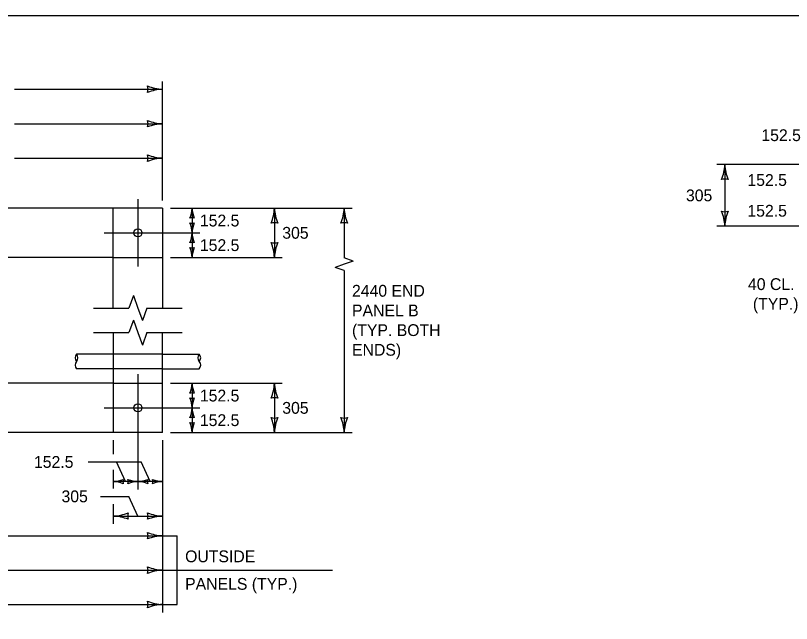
# Model space of a CAD drawing. Extents: x 49991.4 to 50021, y 49987.6 to 50011.4.
# Drawn here: x 50005.475 to 50009.419, y 49995.908 to 49998.999 of the extents above; entities that cross this region are included whole.
import ezdxf

# ---------------------------------------------------------------- set-up
doc = ezdxf.new("R2010")
doc.units = 0
for name, color, linetype in [('Level 1', 7, 'Continuous'), ('Level 2', 7, 'Continuous'), ('Level 3', 7, 'Continuous'), ('Level 4', 7, 'Continuous'), ('Level 5', 7, 'Continuous'), ('Level 6', 7, 'Continuous')]:
    doc.layers.add(name, color=color, linetype=linetype)

msp = doc.modelspace()

# ---------------------------------------------------------------- linework, layer by layer
at = {"layer": 'Level 1'}
for p, q in [((50006.2218, 49998.0191), (50005.1236, 49998.0191)), ((50005.9718, 49997.5116), (50005.9718, 49998.0191)), ((50006.2218, 49998.0191), (50006.2218, 49997.5116)), ((50005.9718, 49997.7691), (50005.1236, 49997.7691)), ((50005.9718, 49997.3866), (50005.9718, 49996.8791)), ((50006.2218, 49996.8791), (50006.2218, 49997.3866)), ((50005.9718, 49997.2773), (50005.7843, 49997.2773)), ((50006.2218, 49997.2773), (50006.4086, 49997.2773)), ((50005.9718, 49997.2023), (50005.7845, 49997.2023)), ((50006.2218, 49997.2023), (50006.4084, 49997.2023)), ((50005.9718, 49997.1291), (50005.1236, 49997.1291)), ((50006.2218, 49996.8791), (50005.1236, 49996.8791))]:
    msp.add_line(p, q, dxfattribs=at)
msp.add_lwpolyline([(49999.3835, 49998.9992), (50016.7501, 49998.9992), (50016.7501, 49987.7988), (49999.3835, 49987.7988)], close=True, dxfattribs=at)
for centre in [(50006.0967, 49997.8941), (50006.0967, 49997.0041)]:
    msp.add_circle(centre, 0.0208, dxfattribs=at)
for centre, radius, start, end in [((50005.8052, 49997.2585), 0.0281, 138.1897, 221.8103), ((50005.7633, 49997.2585), 0.0281, 318.1897, 41.8103), ((50006.4296, 49997.2585), 0.0281, 138.1897, 221.8103), ((50006.3877, 49997.2585), 0.0281, 318.1897, 41.8103), ((50005.8046, 49997.2212), 0.0276, 137.5252, 223.2656), ((50006.3885, 49997.2212), 0.0275, 316.52, 42.6892)]:
    msp.add_arc(centre, radius, start, end, dxfattribs=at)
at = {"layer": 'Level 3'}
for p, q in [((50006.2218, 49998.0591), (50006.2218, 49998.6641)), ((50005.469, 49998.6241), (50006.2218, 49998.6241)), ((50005.469, 49998.4491), (50006.2218, 49998.4491)), ((50005.4689, 49998.2741), (50006.2218, 49998.2741)), ((50009.5801, 49998.2408), (50009.0402, 49998.2408)), ((50009.0802, 49998.2408), (50009.0802, 49997.9282)), ((50006.2618, 49998.0191), (50007.1851, 49998.0191)), ((50006.3718, 49998.0191), (50006.3718, 49997.8941)), ((50006.7906, 49998.0191), (50006.7906, 49997.7691)), ((50007.1451, 49998.0191), (50007.1451, 49997.7668)), ((50009.8825, 49997.9282), (50009.0402, 49997.9282)), ((50006.3718, 49997.8941), (50006.3718, 49997.7691)), ((50006.2618, 49997.7691), (50006.8306, 49997.7691)), ((50007.1908, 49997.7506), (50007.1451, 49997.7668)), ((50007.1451, 49997.7344), (50007.0994, 49997.7182)), ((50007.1908, 49997.7506), (50007.1451, 49997.7344)), ((50007.1451, 49997.702), (50007.0994, 49997.7182)), ((50007.1451, 49997.702), (50007.1451, 49996.8791)), ((50006.2618, 49997.1291), (50006.8306, 49997.1291)), ((50006.3718, 49997.1291), (50006.3718, 49997.0041)), ((50006.7906, 49997.1291), (50006.7906, 49996.8791)), ((50006.3718, 49997.0041), (50006.3718, 49996.8791)), ((50006.2618, 49996.8791), (50007.1851, 49996.8791)), ((50005.9718, 49996.8391), (50005.9718, 49996.7691)), ((50006.2218, 49996.8391), (50006.2218, 49995.9641)), ((50005.8435, 49996.7291), (50006.1125, 49996.7291)), ((50006.0343, 49996.6291), (50005.9875, 49996.7291)), ((50006.1593, 49996.6291), (50006.1125, 49996.7291)), ((50005.9718, 49996.6891), (50005.9718, 49996.5941)), ((50006.0968, 49996.6291), (50005.9718, 49996.6291)), ((50006.2218, 49996.6291), (50006.0968, 49996.6291)), ((50005.906, 49996.5541), (50006.05, 49996.5541)), ((50006.0968, 49996.4541), (50006.05, 49996.5541)), ((50005.9718, 49996.5141), (50005.9718, 49996.4141)), ((50005.9718, 49996.4541), (50006.2218, 49996.4541)), ((50003.8378, 49996.3541), (50006.2218, 49996.3541)), ((50006.2218, 49996.3541), (50006.2968, 49996.3541)), ((50006.2968, 49996.0041), (50006.2968, 49996.3541)), ((50003.8378, 49996.1791), (50006.2218, 49996.1791)), ((50006.2218, 49996.1791), (50007.0861, 49996.1791)), ((50003.8378, 49996.0041), (50006.2218, 49996.0041)), ((50006.2218, 49996.0041), (50006.2968, 49996.0041))]:
    msp.add_line(p, q, dxfattribs=at)
for centre, radius, start, end in [((50006.231, 49998.8462), 0.2223, 247.456, 267.6395), ((50006.0936, 49998.6241), 0.0548, 342.1388, 17.8612), ((50006.2333, 49998.3914), 0.233, 92.8273, 112.0772), ((50006.231, 49998.6712), 0.2223, 247.456, 267.6395), ((50006.0936, 49998.4491), 0.0548, 342.1388, 17.8612), ((50006.2333, 49998.2164), 0.233, 92.8273, 112.0772), ((50006.231, 49998.4962), 0.2223, 247.456, 267.6395), ((50006.0936, 49998.2741), 0.0548, 342.1388, 17.8612), ((50006.2333, 49998.0414), 0.233, 92.8273, 112.0772), ((50008.8581, 49998.25), 0.2223, 337.456, 357.6395), ((50009.3129, 49998.2523), 0.233, 182.8273, 202.0772), ((50009.0802, 49998.1126), 0.0548, 72.1388, 107.8612), ((50006.2237, 49998.0252), 0.1482, 337.456, 357.6395), ((50006.5269, 49998.0268), 0.1553, 182.8273, 202.0772), ((50006.5685, 49998.0283), 0.2223, 337.456, 357.6395), ((50007.0233, 49998.0306), 0.233, 182.8273, 202.0772), ((50006.923, 49998.0283), 0.2223, 337.456, 357.6395), ((50007.3778, 49998.0306), 0.233, 182.8273, 202.0772), ((50009.0802, 49998.0564), 0.0548, 252.1388, 287.8612), ((50008.8475, 49997.9167), 0.233, 2.8273, 22.0772), ((50009.3024, 49997.919), 0.2223, 157.456, 177.6395), ((50006.3718, 49997.9336), 0.0365, 72.1388, 107.8612), ((50006.3718, 49997.9796), 0.0365, 252.1388, 287.8612), ((50006.2167, 49997.8864), 0.1553, 2.8273, 22.0772), ((50006.5199, 49997.888), 0.1482, 157.456, 177.6395), ((50006.7906, 49997.8909), 0.0548, 72.1388, 107.8612), ((50007.1451, 49997.8909), 0.0548, 72.1388, 107.8612), ((50006.2237, 49997.9002), 0.1482, 337.456, 357.6395), ((50006.5269, 49997.9018), 0.1553, 182.8273, 202.0772), ((50006.3718, 49997.8086), 0.0365, 72.1388, 107.8612), ((50006.7906, 49997.8973), 0.0548, 252.1388, 287.8612), ((50006.5579, 49997.7576), 0.233, 2.8273, 22.0772), ((50007.0127, 49997.7599), 0.2223, 157.456, 177.6395), ((50006.3718, 49997.8546), 0.0365, 252.1388, 287.8612), ((50006.2167, 49997.7614), 0.1553, 2.8273, 22.0772), ((50006.5199, 49997.763), 0.1482, 157.456, 177.6395), ((50006.2237, 49997.1352), 0.1482, 337.456, 357.6395), ((50006.5269, 49997.1368), 0.1553, 182.8273, 202.0772), ((50006.5685, 49997.1383), 0.2223, 337.456, 357.6395), ((50007.0233, 49997.1406), 0.233, 182.8273, 202.0772), ((50006.3718, 49997.0436), 0.0365, 72.1388, 107.8612), ((50006.3718, 49997.0896), 0.0365, 252.1388, 287.8612), ((50006.2167, 49996.9964), 0.1553, 2.8273, 22.0772), ((50006.5199, 49996.998), 0.1482, 157.456, 177.6395), ((50006.7906, 49997.0009), 0.0548, 72.1388, 107.8612), ((50006.2237, 49997.0102), 0.1482, 337.456, 357.6395), ((50006.5269, 49997.0118), 0.1553, 182.8273, 202.0772), ((50006.3718, 49996.9186), 0.0365, 72.1388, 107.8612), ((50006.7906, 49997.0073), 0.0548, 252.1388, 287.8612), ((50006.5579, 49996.8676), 0.233, 2.8273, 22.0772), ((50007.0127, 49996.8699), 0.2223, 157.456, 177.6395), ((50007.1451, 49997.0073), 0.0548, 252.1388, 287.8612), ((50006.9124, 49996.8676), 0.233, 2.8273, 22.0772), ((50007.3672, 49996.8699), 0.2223, 157.456, 177.6395), ((50006.3718, 49996.9646), 0.0365, 252.1388, 287.8612), ((50006.2167, 49996.8714), 0.1553, 2.8273, 22.0772), ((50006.5199, 49996.873), 0.1482, 157.456, 177.6395), ((50005.9641, 49996.7842), 0.1553, 272.8273, 292.0772), ((50005.9657, 49996.481), 0.1482, 67.456, 87.6395), ((50006.0573, 49996.6291), 0.0365, 162.1388, 197.8612), ((50006.1029, 49996.7772), 0.1482, 247.456, 267.6395), ((50006.0113, 49996.6291), 0.0365, 342.1388, 17.8612), ((50006.1045, 49996.474), 0.1553, 92.8273, 112.0772), ((50006.0891, 49996.7842), 0.1553, 272.8273, 292.0772), ((50006.0907, 49996.481), 0.1482, 67.456, 87.6395), ((50006.1823, 49996.6291), 0.0365, 162.1388, 197.8612), ((50006.2279, 49996.7772), 0.1482, 247.456, 267.6395), ((50006.1363, 49996.6291), 0.0365, 342.1388, 17.8612), ((50006.2295, 49996.474), 0.1553, 92.8273, 112.0772), ((50005.9603, 49996.6868), 0.233, 272.8273, 292.0772), ((50006.1, 49996.4541), 0.0548, 162.1388, 197.8612), ((50006.231, 49996.6762), 0.2223, 247.456, 267.6395), ((50006.0936, 49996.4541), 0.0548, 342.1388, 17.8612), ((50005.9626, 49996.232), 0.2223, 67.456, 87.6395), ((50006.2333, 49996.2214), 0.233, 92.8273, 112.0772), ((50006.231, 49996.5762), 0.2223, 247.456, 267.6395), ((50006.0936, 49996.3541), 0.0548, 342.1388, 17.8612), ((50006.2333, 49996.1214), 0.233, 92.8273, 112.0772), ((50006.231, 49996.4012), 0.2223, 247.456, 267.6395), ((50006.0936, 49996.1791), 0.0548, 342.1388, 17.8612), ((50006.2333, 49995.9464), 0.233, 92.8273, 112.0772), ((50006.231, 49996.2262), 0.2223, 247.456, 267.6395), ((50006.0936, 49996.0041), 0.0548, 342.1388, 17.8612), ((50006.2333, 49995.7714), 0.233, 92.8273, 112.0772)]:
    msp.add_arc(centre, radius, start, end, dxfattribs=at)
at = {"layer": 'Level 4'}
for p, q in [((50005.9718, 49997.7691), (50006.2218, 49997.7691)), ((50006.2218, 49997.2773), (50005.9718, 49997.2773)), ((50006.2218, 49997.2023), (50005.9718, 49997.2023)), ((50005.9718, 49997.1291), (50006.2218, 49997.1291))]:
    msp.add_line(p, q, dxfattribs=at)
at = {"layer": 'Level 5'}
for p, q in [((50006.0968, 49998.0649), (50006.0968, 49997.7232)), ((50005.9259, 49997.8941), (50006.4118, 49997.8941)), ((50006.0968, 49997.1749), (50006.0968, 49996.5891)), ((50005.9259, 49997.0041), (50006.4118, 49997.0041))]:
    msp.add_line(p, q, dxfattribs=at)
at = {"layer": 'Level 6'}
for p, q in [((50006.0741, 49997.5756), (50006.0514, 49997.5116)), ((50006.0741, 49997.5756), (50006.0968, 49997.5116)), ((50005.8718, 49997.5116), (50006.0514, 49997.5116)), ((50006.0968, 49997.5116), (50006.1195, 49997.4476)), ((50006.1422, 49997.5116), (50006.1195, 49997.4476)), ((50006.1422, 49997.5116), (50006.3218, 49997.5116)), ((50006.0741, 49997.4506), (50006.0514, 49997.3866)), ((50006.0741, 49997.4506), (50006.0968, 49997.3866)), ((50005.8718, 49997.3866), (50006.0514, 49997.3866)), ((50006.0968, 49997.3866), (50006.1195, 49997.3226)), ((50006.1422, 49997.3866), (50006.1195, 49997.3226)), ((50006.1422, 49997.3866), (50006.3218, 49997.3866))]:
    msp.add_line(p, q, dxfattribs=at)

# ---------------------------------------------------------------- texts
at = {"layer": 'Level 2'}
for s, p in [('152.5', (50009.2659, 49998.3606)), ('152.5', (50009.195, 49998.1326)), ('305', (50008.8827, 49998.0545)), ('152.5', (50009.195, 49997.9764)), ('152.5', (50006.4118, 49997.9266)), ('305', (50006.8306, 49997.8642)), ('152.5', (50006.4118, 49997.8016)), ('40 CL.', (50009.1979, 49997.6032)), ('2440 END', (50007.1851, 49997.5694)), ('PANEL B', (50007.1851, 49997.4694)), ('(TYP.)', (50009.2229, 49997.5032)), ('(TYP. BOTH', (50007.1851, 49997.3694)), ('ENDS)', (50007.1851, 49997.2694)), ('152.5', (50006.4118, 49997.0366)), ('305', (50006.8306, 49996.9741)), ('152.5', (50006.4118, 49996.9116)), ('152.5', (50005.5684, 49996.6991)), ('305', (50005.7084, 49996.5241)), ('OUTSIDE', (50006.3368, 49996.2191)), ('PANELS (TYP.)', (50006.3368, 49996.0791))]:
    msp.add_text(s, height=0.06, dxfattribs=at).set_placement(p)

doc.saveas('drawing.dxf')
